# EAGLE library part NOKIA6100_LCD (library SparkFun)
Nokia 6100 Color LCD Schematic element and footprint production proven but could use some touching up. Spark Fun Electronics SKU : LCD-Color-Nokia. Mating SMD connector : LCD-Color-Connector
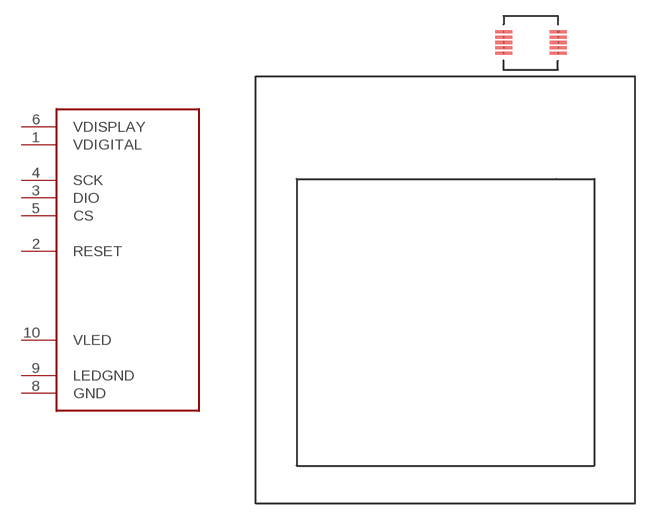
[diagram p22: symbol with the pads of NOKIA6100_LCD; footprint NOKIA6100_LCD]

Designator prefix -

## NOKIA6100_LCD  [NOKIA6100_LCD]
1  VDIGITAL
2  RESET
3  DIO
4  SCK
5  CS
6  VDISPLAY
8  GND
9  LEDGND
10  VLED

## Footprint NOKIA6100_LCD (pad centres in mm)
smd 1.6 x 0.3: 1 24.255,44.311; 2 24.255,43.811; 3 24.255,43.311; 4 24.255,42.811; 5 24.255,42.311; 6 29.389,42.303; 7 29.389,42.803; 8 29.389,43.303; 9 29.389,43.803; 10 29.389,44.303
